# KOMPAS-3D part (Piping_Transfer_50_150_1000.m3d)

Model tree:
1. Plane XY
2. Plane ZX
3. Plane ZY
4. X Axis
5. Y Axis
6. Z Axis
7. Origin
8. Sketch:1
9. Sketch:2
10. Parallel Plane:1
11. Parallel Plane:2
12. Parallel Plane:3
13. Sketch:3
14. Sketch:4
15. Sketch:5
16. Loft:1  (labels: Толщина стенки 1; Толщина стенки 2)
17. Sketch:6
18. Sketch:7
19. Sketch:8
20. Sketch:9
21. Cut-Loft:1  (labels: Толщина стенки 1; Толщина стенки 2)
22. Attachment Point:1
23. Attachment Point:2

Expressions: D*0.5; D1*0.5; D-2*T; D1-2*T1; L*0.15
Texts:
  Transfer Dn 50-150
  Steel ASTM A295
  Three Point Plane
  Plane at Angle
  Line and Point Plane
  Axis through Two Vertices
  Axis of Feature
  Axis of Conical Surface
  Axis through Edge
  Приклеить элемент выдавливания
  Приклеить элемент вращения
  Приклеить кинематический элемент
  Приклеить элемент по сечениям
  Trim by Surface
  Trim by Sketch
  Feature with No History
  Intersection Axis of Two Planes
  Two Line Plane
  Line and Face Plane
  Bend by line
  Hole in sheet body
  Cut in sheet body
  Point in CM
  Linear Dimension from Line to Point
  Surface Finish Symbol
  Geometric Tolerance Symbol
  Текст на чертеже
  Линия-выноска #1
  Линия-выноска #2
  Линия-выноска #3
  Отклонения формы и база
  Марка координационной оси
  Марка/позиционное обозначение с линией-выноской
  Марка/позиционное обозначение на линии
  Марка/позиционное обозначение без линии-выноски
  Толщина стенки 1
  Толщина стенки 2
